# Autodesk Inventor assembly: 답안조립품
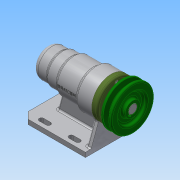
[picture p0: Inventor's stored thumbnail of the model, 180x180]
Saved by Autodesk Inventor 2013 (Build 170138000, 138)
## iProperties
Created: 2017-09
Part Number: 답안조립품
Document SubType Name: Assembly
Designer: Administrator
Author: Administrator
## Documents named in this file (12)
- C:\Users\Administrator\Desktop\470908V1011\답안조립품.iam
- C:\Users\Administrator\Desktop\470908V1011\본체.ipt
- C:\Users\Administrator\Desktop\470908V1011\커버.ipt
- C:\Users\Administrator\Desktop\470908V1011\축.ipt
- C:\Users\Administrator\Desktop\470908V1011\베어링 6004.ipt
- C:\Users\Administrator\Desktop\470908V1011\어댑터슬리브.ipt
- C:\Users\Administrator\Desktop\470908V1011\베어링 51202.ipt
- C:\Users\Administrator\Desktop\470908V1011\키 5 x 5 x 16.ipt
- C:\Users\Administrator\Desktop\470908V1011\V벨트풀리.ipt
- C:\Users\Administrator\Desktop\470908V1011\멈춤나사 M3x8.ipt
- C:\Users\Administrator\Desktop\470908V1011\볼트 M4 x 12.ipt
- C:\Users\Administrator\Desktop\470908V1011\오일 실 20x35x7.ipt
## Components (1 placed, 1 different names)
1. V벨트풀리:1
